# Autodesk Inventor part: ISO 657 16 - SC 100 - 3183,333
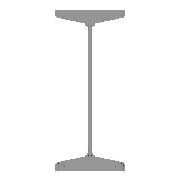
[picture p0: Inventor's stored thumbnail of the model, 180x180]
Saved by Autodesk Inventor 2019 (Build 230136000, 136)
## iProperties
_CCFamilyMember: 1
_CCFamilyDisplayName: ISO 657/16 - 1980 - Poutres en acier laminées à chaud - Partie 16: profilés en H (série métrique) - Cotes et propriétés de section
_FrameMemberDoc: Frame Member File
_Version: 15.0.0
_GetPNFromCC: 1
Created: 2018-07
Part Number: ISO 657 16 - SC 100 - 3183,333
Material: Acier, doux
Description: Poutres en acier laminées à chaud - Partie 16: profilés en H (série métrique) - Cotes et propriétés de section
Document SubType Name: Modeling
Standard: ISO
Designer: Fabian Perrée
Standard Revision: First edition 1980-02-15
Standards Organization: ISO
Language: fr-FR
Size Designation: SC 100
Categories: <MemberInstance><Categories><Category DisplayName="Profilés" InternalName="089c4875-fa83-4c05-b084-43b9cc11f5ed" Mnemonic="GRDR"><CategoryParameter DisplayName=
Stock Number: SC 100
Density: 7.85 g/cm^3
Appearance: Semi-poli
Mass: 62799.5 g
Surface Area: 17060.8 cm^2
Volume: 7999.94 cm^3
IsCustomPart: 1
G_W: 100,000 mm
G_H: 100,000 mm
+C8570A6E-3ADF-402B-AF4B-F69D73FB0D4A+DETAILDECOUPE1: Angle de coupe 67,38 deg
+12B5BAF0-3E22-4404-8C3D-A4FF2A8CEEA4+DETAILDECOUPE2: Angle de coupe 67,38 deg
G_L: 3183,333 mm
Author: Fabian Perrée
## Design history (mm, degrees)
node "Plan de départ"
node "Plan de fin"
sketch "Esquisse"
  geometry: L1 (-3, 0)-(-3, -26.266); L2 (-13.33, -38.149)-(-44.835, -42.577); L3 (-50, -48.518)-(-50, -50); L4 (-50, -50)-(0, -50); L5 (-26.5, -50)-(-26.5, -40); L6 (-61.333, 0)-(81.777, 0); L7 (0, 0)-(0, -50); L8 (0, -60)-(0, 80); L9 (3, 0)-(3, -26.266); L10 (13.33, -38.149)-(44.835, -42.577); L11 (50, -48.518)-(50, -50); L12 (50, -50)-(0, -50); L13 (-3, 0)-(0, 0); L14 (-3, 0)-(-3, 26.266); L15 (-13.33, 38.149)-(-44.835, 42.577); L16 (-50, 48.518)-(-50, 50); L17 (-50, 50)-(0, 50); L18 (50, 48.518)-(50, 50); L19 (13.33, 38.149)-(44.835, 42.577); L20 (3, 0)-(3, 26.266); L21 (50, 50)-(0, 50); L22 (0, 108)-(0, -88) reference; L23 (-89.955, 0)-(110.399, 0) reference; A1 r 6 centre (-44, 48.518) between (-50, 48.518) and (-44.835, 42.577); A2 r 6 centre (44, 48.518) between (44.835, 42.577) and (50, 48.518); A3 r 6 centre (44, -48.518) between (50, -48.518) and (44.835, -42.577); A4 r 6 centre (-44, -48.518) between (-44.835, -42.577) and (-50, -48.518); A5 r 12 centre (-15, 26.266) between (-3, 26.266) and (-13.33, 38.149); A6 r 12 centre (15, 26.266) between (13.33, 38.149) and (3, 26.266); A7 r 12 centre (15, -26.266) between (3, -26.266) and (13.33, -38.149); A8 r 12 centre (-15, -26.266) between (-13.33, -38.149) and (-3, -26.266); 14 further points
  constraints: 42 end point, 24 point on line, 17 symmetric about line, 16 point on circle, 16 tangent, 8 centre point, 6 equal radius, 4 collinear, 2 perpendicular, 12 other
  dimensions: "d1" = 10 vertical distance of L3.end L5.end (= G_T1); "d2" = 23.5 distance between parallel lines of L5 L3 (= -0.25 x G_T + 0.25 x G_W); "d3" = 3 distance between parallel lines of L1 L7 (= 0.5 x G_T); "d4" = 50 distance between parallel lines of L7 L3 (= 0.5 x G_W); "d9" = 50 distance from line of L1.start L4 (= 0.5 x G_H); "d14" = 98 deg angle of L2 L1 (= G_NG); "d15" = 6 radius of A1 (= G_ER); "d16" = 12 radius of A5 (= G_IR)
extrude "Corps" new body sketch "Esquisse" stored distance "d5" = 3183.33333 (= G_L); taper "d6" = 0 deg
node "Driven Length"
  sketch "Sketch3"
    geometry: L1 (0, 0)-(10, 0) reference
    constraints: 2 end point, 1 horizontal
  workplane "Work Plane3"
  sketch "Sketch4"
    geometry: L1 (-2, 0)-(12, 0) reference; L2 (-2, 3183.333)-(12, 3183.333) reference
    dimensions: "d20" = 3183.33333 distance between parallel lines of L1 L2 (derived)
node "Plan de construction4"
feature "Scission1"
node "Plan de construction5"
feature "Scission2"
body "Solid1"
other parameters: "G_W" = 100 (= G_H) [user parameter; used in 2 equation terms], "G_H" = 100 [user parameter; used in 2 equation terms], "G_T" = 6 [user parameter; used in 2 equation terms], "G_T1" = 10 [user parameter; used in 1 equation term], "G_L" = 3183.33333 (= d20) [user parameter; used in 1 equation term], "G_ER" = 6 [user parameter; used in 1 equation term], "G_IR" = 12 [user parameter; used in 1 equation term], "G_NG" = 98 deg [user parameter; used in 1 equation term], "G_OFFSET_START" = 0 [user parameter; used in 1 equation term], "G_OFFSET_END" = -66.66667 [user parameter; used in 1 equation term], "d17" = 0 (computed from G_OFFSET_START), "d18" = 3183.33333 (= G_OFFSET_END + B_L), "d19" = 90 deg
